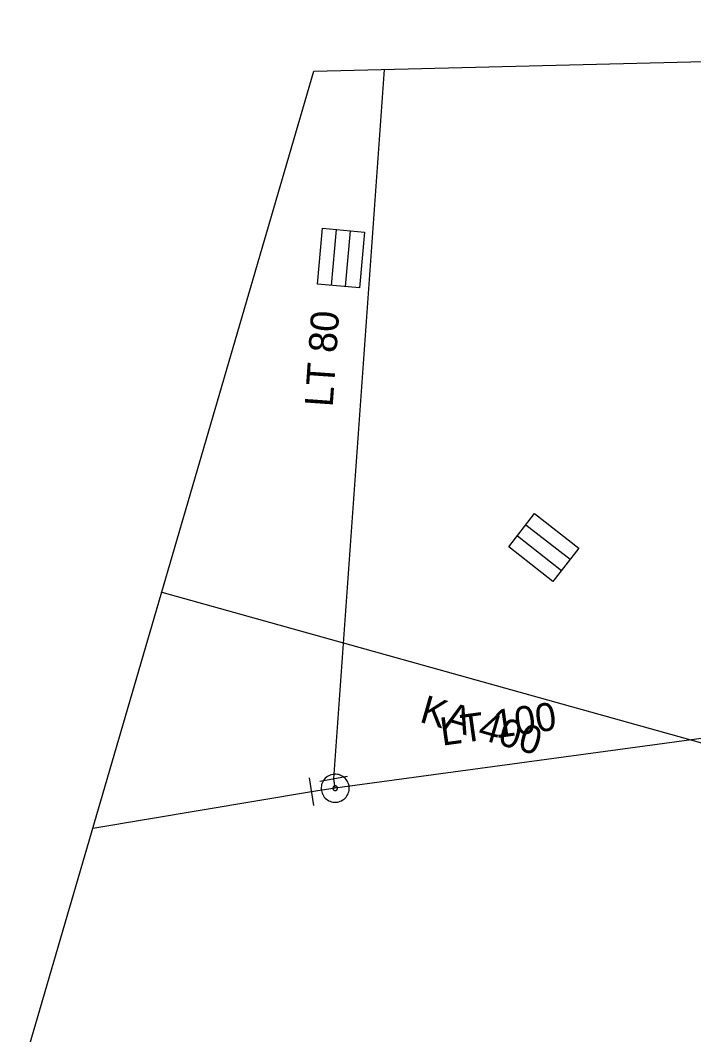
# Model space of a CAD drawing. Extents: x -725807 to -725723.1, y -978165.9 to -978101.2.
# Drawn here: x -725807.01 to -725783, y -978137.33 to -978101.16 of the extents above; entities that cross this region are included whole.
import ezdxf

# ---------------------------------------------------------------- set-up
doc = ezdxf.new("R2010")
doc.units = 0
for name, color, linetype in [('Vrstva 1', 7, 'Continuous'), ('Vrstva 14', 7, 'Continuous'), ('Vrstva 17', 7, 'Continuous'), ('Vrstva 22', 7, 'Continuous'), ('Vrstva 34', 7, 'Continuous'), ('Vrstva 47', 7, 'Continuous')]:
    doc.layers.add(name, color=color, linetype=linetype)

msp = doc.modelspace()

# ---------------------------------------------------------------- linework, layer by layer
at = {"layer": 'Vrstva 1'}
msp.add_lwpolyline([(-725807.01, -978138.838), (-725796.543, -978102.971), (-725723.134, -978101.157), (-725729.135, -978159.354), (-725758.583, -978165.913), (-725792.915, -978158.237)], close=True, dxfattribs=at)
at = {"layer": 'Vrstva 14'}
for points in [[(-725801.965, -978121.55), (-725766.42, -978131.467)], [(-725795.783, -978128.538), (-725795.835, -978128.208)], [(-725795.783, -978128.538), (-725796.63, -978128.664)]]:
    msp.add_lwpolyline(points, dxfattribs=at)
at = {"layer": 'Vrstva 17'}
for points in [[(-725795.835, -978128.208), (-725794.027, -978102.909)], [(-725772.166, -978126.454), (-725781.945, -978126.655), (-725795.783, -978128.538)], [(-725796.63, -978128.664), (-725804.422, -978129.97)]]:
    msp.add_lwpolyline(points, dxfattribs=at)
at = {"layer": 'Vrstva 22'}
for points in [[(-725796.416, -978110.564), (-725796.236, -978108.572), (-725794.742, -978108.706), (-725794.922, -978110.698), (-725796.416, -978110.564)], [(-725795.918, -978110.608), (-725795.738, -978108.616)], [(-725795.42, -978110.653), (-725795.24, -978108.661)], [(-725788.673, -978118.748), (-725787.099, -978119.983), (-725788.025, -978121.163), (-725789.599, -978119.928), (-725788.673, -978118.748)], [(-725788.982, -978119.142), (-725787.408, -978120.376)], [(-725789.29, -978119.535), (-725787.717, -978120.77)]]:
    msp.add_lwpolyline(points, dxfattribs=at)
at = {"layer": 'Vrstva 34'}
for points in [[(-725796.708, -978128.17), (-725796.552, -978129.157)], [(-725795.342, -978128.12), (-725796.327, -978128.294)]]:
    msp.add_lwpolyline(points, dxfattribs=at)
at = {"layer": 'Vrstva 47'}
for points in [[(-725795.289, -978128.46), (-725795.3, -978128.409), (-725795.316, -978128.359), (-725795.337, -978128.311), (-725795.363, -978128.266), (-725795.394, -978128.223), (-725795.429, -978128.184), (-725795.468, -978128.15), (-725795.51, -978128.119), (-725795.555, -978128.093), (-725795.603, -978128.071), (-725795.653, -978128.054), (-725795.704, -978128.044), (-725795.756, -978128.038), (-725795.808, -978128.038), (-725795.86, -978128.044), (-725795.911, -978128.055), (-725795.961, -978128.071), (-725796.01, -978128.092), (-725796.054, -978128.118), (-725796.097, -978128.149), (-725796.136, -978128.184), (-725796.171, -978128.223), (-725796.202, -978128.265), (-725796.228, -978128.31), (-725796.249, -978128.358), (-725796.266, -978128.408), (-725796.277, -978128.459), (-725796.282, -978128.511), (-725796.282, -978128.563), (-725796.276, -978128.615), (-725796.265, -978128.666), (-725796.249, -978128.716), (-725796.229, -978128.765), (-725796.202, -978128.809), (-725796.171, -978128.852), (-725796.137, -978128.891), (-725796.098, -978128.926), (-725796.056, -978128.957), (-725796.01, -978128.983), (-725795.962, -978129.004), (-725795.912, -978129.021), (-725795.862, -978129.032), (-725795.809, -978129.037), (-725795.757, -978129.037), (-725795.705, -978129.031), (-725795.654, -978129.02), (-725795.604, -978129.004), (-725795.556, -978128.984), (-725795.511, -978128.957), (-725795.468, -978128.926), (-725795.429, -978128.892), (-725795.395, -978128.853), (-725795.364, -978128.811), (-725795.338, -978128.765), (-725795.316, -978128.717), (-725795.299, -978128.667), (-725795.289, -978128.617), (-725795.283, -978128.564), (-725795.283, -978128.512), (-725795.289, -978128.46)], [(-725795.701, -978128.525), (-725795.703, -978128.516), (-725795.706, -978128.508), (-725795.709, -978128.501), (-725795.714, -978128.493), (-725795.719, -978128.486), (-725795.725, -978128.48), (-725795.731, -978128.474), (-725795.738, -978128.469), (-725795.745, -978128.465), (-725795.753, -978128.461), (-725795.762, -978128.458), (-725795.77, -978128.457), (-725795.778, -978128.456), (-725795.786, -978128.455), (-725795.795, -978128.456), (-725795.804, -978128.458), (-725795.812, -978128.461), (-725795.819, -978128.464), (-725795.827, -978128.469), (-725795.834, -978128.474), (-725795.84, -978128.48), (-725795.846, -978128.486), (-725795.851, -978128.493), (-725795.856, -978128.501), (-725795.859, -978128.508), (-725795.862, -978128.517), (-725795.863, -978128.525), (-725795.864, -978128.533), (-725795.865, -978128.541), (-725795.864, -978128.55), (-725795.862, -978128.559), (-725795.859, -978128.567), (-725795.856, -978128.574), (-725795.851, -978128.582), (-725795.846, -978128.589), (-725795.841, -978128.595), (-725795.834, -978128.601), (-725795.827, -978128.606), (-725795.819, -978128.611), (-725795.812, -978128.614), (-725795.803, -978128.617), (-725795.795, -978128.618), (-725795.787, -978128.619), (-725795.779, -978128.62), (-725795.77, -978128.619), (-725795.761, -978128.617), (-725795.753, -978128.614), (-725795.746, -978128.611), (-725795.738, -978128.606), (-725795.731, -978128.601), (-725795.725, -978128.596), (-725795.719, -978128.589), (-725795.714, -978128.582), (-725795.71, -978128.575), (-725795.706, -978128.567), (-725795.703, -978128.558), (-725795.702, -978128.55), (-725795.701, -978128.542), (-725795.7, -978128.534), (-725795.701, -978128.525)]]:
    msp.add_lwpolyline(points, dxfattribs=at)

# ---------------------------------------------------------------- texts
at = {"layer": 'Vrstva 1'}
for s, rotation, p in [('LT 80 ', 86, (-725795.875, -978114.962)), ('KA 400', 344, (-725792.813, -978126.164)), ('LT 100', 8, (-725791.97, -978127.025))]:
    msp.add_text(s, height=1, rotation=rotation, dxfattribs=at).set_placement(p)

doc.saveas('drawing.dxf')
